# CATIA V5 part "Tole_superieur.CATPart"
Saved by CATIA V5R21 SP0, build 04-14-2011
Part number: Tole_superieur
Bounding box of the stored display mesh (mm): x -106 to 106, y -200 to 152, z -3 to 17
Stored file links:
  C:\Users\zerma\Pictures\Stage Stomate\Tole_superieur.CATPart
  C:\Users\zerma\Pictures\Stage Stomate\Part1.CATPart
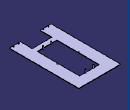
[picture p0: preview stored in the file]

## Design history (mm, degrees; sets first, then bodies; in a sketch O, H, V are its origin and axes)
Body1 (main body)
  DatumCurve1 to DatumCurve4
  Sketch1 on xy-plane, origin (0, 0, 0), H (1, 0, 0), V (0, 1, 0)
    line L1 (0, 152) -> (106, 152)
    line L2 (106, 152) -> (106, -200)
    line L3 (50, 100) -> (0, 100)
    line L4 (50, -200) -> (106, -200)
    line L5 (50, -200) -> (50, -140)
    line L6 (50, 100) -> (50, -115)
    line L7 (50, -115) -> (0, -115)
    line L8 (50, -140) -> (0, -140)
    line L9 (0, -115) -> (0, -140)
    line L10 (0, 152) -> (0, 100)
    length L2 = 352
    length L3 = 50
    length L4 = 56
    length L1 = 106
    length L6 = 215
    length L7 = 50
    length L5 = 60
    length L10 = 52
    horizontal: L1 H, L3 H, L4 H, L7 H, L8 H
    vertical: L2 V, L5 V, L6 V, L9 V, L10 V
  Pad1: profile Sketch1, direction (0, 0, 1), length 2
  Sketch2 on end face of Pad1, origin (0, 0, 2), H (1, 0, 0), V (0, 1, 0)
    circle A1 centre (20, 100) radius 2.5
    point P1 (20, 100)
    point P2 (-20, 100)
    reference projected line E1 (50, 100) -> (50, -115) from edge [face of Pad1 from Sketch1.L6 | end face of Pad1]
    reference projected line E2 (106, 152) -> (0, 152) from edge [face of Pad1 from Sketch1.L1 | end face of Pad1]
    distance P1 E1 = 30
    distance P1 E2 = 52
  Pad2: profile Sketch2, direction (0, 0, -1), length 5
  Pad3: profile Sketch2, direction (0, 0, 1), length 15
  Sketch3 on face of Pad2, origin (0, 0, 2), H (1, 0, 0), V (0, 1, 0)
    circle A1 centre (63, -195.5) radius 2.5
    point P1 (63, -195.5)
    circle A2 centre (88, -195.5) radius 2.5
    point P2 (88, -195.5)
    reference projected line E1 (50, -200) -> (106, -200) from edge [face of Pad1 from Sketch1.L4 | end face of Pad1]
    reference projected line E2 (50, -200) -> (106, -200) from edge [face of Pad1 from Sketch1.L4 | end face of Pad1]
    reference projected line E3 (106, -200) -> (106, 152) from edge [face of Pad1 from Sketch1.L2 | end face of Pad1]
    radius A2 = 2.5
    radius A1 = 2.5
    distance P2 E1 = 4.5
    distance P1 E2 = 4.5
    distance P2 E3 = 18
    distance P2 P1 = 25
  Pocket1: profile Sketch3, direction (0, 0, -1), length 2
  DatumCurve5
  Sketch4 on face of Pad2, origin (0, 0, 2), H (1, 0, 0), V (0, 1, 0)
    circle A1 centre (20, -115) radius 2.5
    reference projected circle E1 centre (20, -115) radius 2.5 from edge of DatumCurve5
    reference projected circle E2 centre (20, -115) radius 2.5 from edge of DatumCurve5
    concentricity: E1 A1
    coincidence: E2 A1
  Pad4: profile Sketch4, direction (0, 0, -1), length 5
  Pad5: profile Sketch4, direction (0, 0, 1), length 9
  Mirror1: of Pad1, Pad2, Pad3, Sketch2, Pocket1, Pad4, Pad5, Sketch4, about yz-plane
  Sketch5 on face of Mirror1, origin (0, 0, 2), H (1, 0, 0), V (0, 1, 0)
    circle A1 centre (55, -4.25) radius 1
    point P1 (55, -4.25)
    reference projected line E1 (0, 100) -> (50, 100) from edge [face of Pad1 from Sketch1.L3 | face of Mirror1]
    circle A2 centre (55, -10.75) radius 1
    point P2 (55, -10.75)
    reference projected line E2 (50, 100) -> (50, -115) from edge [face of Pad1 from Sketch1.L6 | end face of Pad1]
    radius A1 = 1
    distance P1 E1 = 104.25
    radius A2 = 1
    distance P2 P1 = 6.5
    distance P1 E2 = 5
  Pocket2: profile Sketch5, direction (0, 0, -1), length 2
  Mirror2: of Pocket2, about yz-plane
